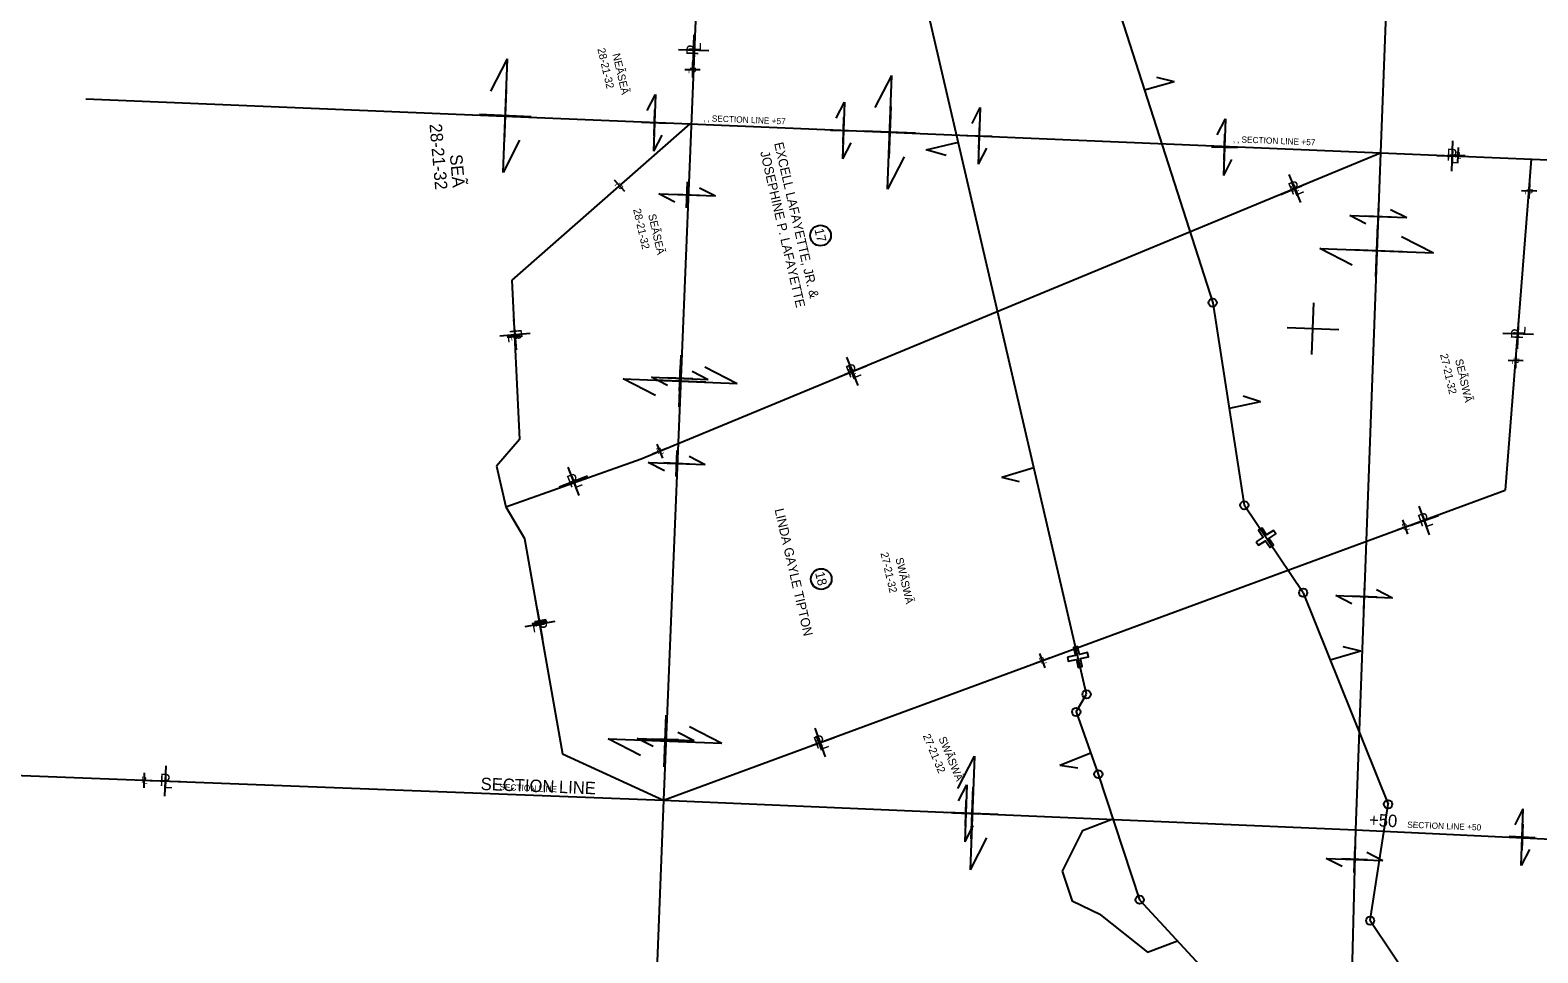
# Model space of a CAD drawing. Extents: x 2814293 to 2835768, y 121185 to 156337.
# Drawn here: x 2819203 to 2822119, y 125490 to 127276 of the extents above; entities that cross this region are included whole.
import ezdxf

# ---------------------------------------------------------------- set-up
doc = ezdxf.new("R2010")
doc.units = 0
for name, color, linetype in [('Default', 7, 'Continuous'), ('Photo-Retaining wall', 7, 'Continuous'), ('Roadway-Alignment notes', 7, 'Continuous'), ('Roadway-Ditches', 7, 'Continuous'), ('Roadway-Edge of pavement', 7, 'Continuous'), ('Roadway-Edge of shoulder', 7, 'Continuous'), ('Roadway-Entrances', 7, 'Continuous'), ('Roadway-New rw', 7, 'Continuous'), ('Roadway-Safety', 7, 'Continuous'), ('Roadway-Temporary easement', 7, 'Continuous'), ('Roadway-Walls', 7, 'Continuous'), ('Scratch-2', 7, 'Continuous'), ('Scratch-5', 7, 'Continuous'), ('Text-New rw label', 7, 'Continuous'), ('Traffic_Control-Traffic barriers', 7, 'Continuous')]:
    doc.layers.add(name, color=color, linetype=linetype)

msp = doc.modelspace()

# ---------------------------------------------------------------- linework, layer by layer
at = {"layer": 'Default'}
for p, q in [((2821682.3, 126648.2), (2821686.1, 126748.2)), ((2821734.2, 126696.2), (2821634.2, 126700.1))]:
    msp.add_line(p, q, dxfattribs=at)
at = {"layer": 'Roadway-Ditches'}
for centre in [(2820731.9, 126878.4), (2820733.3, 126213.7)]:
    msp.add_circle(centre, 20, dxfattribs=at)
at = {"layer": 'Roadway-Edge of pavement'}
for p, q in [((2820396.7, 127120.4), (2820412.6, 127151.6)), ((2820412.6, 127151.6), (2820408.8, 127041.7)), ((2820409.8, 127071.6), (2820411.6, 127121.6)), ((2820762.3, 127105.3), (2820778.2, 127136.5)), ((2820778.2, 127136.5), (2820774.3, 127026.6)), ((2821025, 127095), (2821040.9, 127126.2)), ((2821040.9, 127126.2), (2821037, 127016.3)), ((2820385.7, 127097.5), (2820435.7, 127095.7)), ((2820410.7, 127096.6), (2820410.7, 127096.6)), ((2820775.3, 127056.6), (2820777.1, 127106.5)), ((2821038, 127046.3), (2821039.8, 127096.2)), ((2821499.1, 127073.2), (2821515, 127104.3)), ((2821515, 127104.3), (2821511.1, 126994.4)), ((2820424.7, 127072.8), (2820408.8, 127041.7)), ((2820751.2, 127082.4), (2820801.2, 127080.7)), ((2820790.2, 127057.8), (2820774.3, 127026.6)), ((2820776.2, 127081.6), (2820776.2, 127081.6)), ((2821013.9, 127072.1), (2821063.9, 127070.4)), ((2821038.9, 127071.2), (2821038.9, 127071.2)), ((2821512.2, 127024.4), (2821513.9, 127074.4)), ((2821052.9, 127047.4), (2821037, 127016.3)), ((2821488.1, 127050.3), (2821538, 127048.5)), ((2821527, 127025.6), (2821511.1, 126994.4)), ((2821513.1, 127049.4), (2821513.1, 127049.4)), ((2820472.8, 126932.1), (2820474.7, 126982.1)), ((2820497.6, 126971), (2820528.7, 126954.9)), ((2820418.8, 126959.2), (2820528.7, 126954.9)), ((2820449.9, 126943.2), (2820418.8, 126959.2)), ((2820498.7, 126956.1), (2820448.8, 126958)), ((2820473.7, 126957.1), (2820473.7, 126957.1)), ((2821809.5, 126890.1), (2821811.5, 126940.1)), ((2821755.6, 126917.2), (2821865.5, 126913)), ((2821786.7, 126901.2), (2821755.6, 126917.2)), ((2821835.5, 126914.1), (2821785.5, 126916.1)), ((2821810.5, 126915.1), (2821810.5, 126915.1)), ((2821834.4, 126929), (2821865.5, 126913)), ((2820458.9, 126577.2), (2820460.8, 126627.2)), ((2820483.7, 126616), (2820514.8, 126600)), ((2820404.9, 126604.3), (2820514.8, 126600)), ((2820436, 126588.3), (2820404.9, 126604.3)), ((2820484.9, 126601.2), (2820434.9, 126603.1)), ((2820459.9, 126602.2), (2820459.9, 126602.2)), ((2820452.7, 126412.3), (2820454.7, 126462.3)), ((2820477.5, 126451.2), (2820508.6, 126435.2)), ((2820398.7, 126439.4), (2820508.6, 126435.2)), ((2820429.8, 126423.4), (2820398.7, 126439.4)), ((2820478.7, 126436.3), (2820428.7, 126438.3)), ((2820453.7, 126437.3), (2820453.7, 126437.3)), ((2821728.5, 126181.9), (2821838.4, 126177.6)), ((2821759.6, 126165.9), (2821728.5, 126181.9)), ((2821808.4, 126178.8), (2821758.5, 126180.7)), ((2821782.5, 126154.8), (2821784.4, 126204.7)), ((2821783.4, 126179.7), (2821783.4, 126179.7)), ((2821807.3, 126193.6), (2821838.4, 126177.6)), ((2820431.2, 125878.3), (2820433.1, 125928.3)), ((2820456, 125917.2), (2820487.1, 125901.1)), ((2820377.2, 125905.4), (2820487.1, 125901.1)), ((2820408.3, 125889.4), (2820377.2, 125905.4)), ((2820457.2, 125902.3), (2820407.2, 125904.2)), ((2820432.2, 125903.3), (2820432.2, 125903.3)), ((2820998.9, 125784.3), (2821014.9, 125815.4)), ((2821014.9, 125815.4), (2821010.7, 125705.5)), ((2821011.9, 125735.5), (2821013.8, 125785.4)), ((2820987.8, 125761.4), (2821037.8, 125759.5)), ((2821012.8, 125760.4), (2821012.8, 125760.4)), ((2822075.1, 125738.1), (2822091.1, 125769.3)), ((2822086.9, 125659.3), (2822091.1, 125769.3)), ((2821026.7, 125736.6), (2821010.7, 125705.5)), ((2822114, 125713.3), (2822064, 125715.3)), ((2822090, 125739.3), (2822088, 125689.3)), ((2822089, 125714.3), (2822089, 125714.3)), ((2821763.8, 125646.1), (2821765.7, 125696.1)), ((2821788.6, 125685), (2821819.7, 125669)), ((2822102.9, 125690.5), (2822086.9, 125659.3)), ((2821709.8, 125673.2), (2821819.7, 125669)), ((2821740.9, 125657.2), (2821709.8, 125673.2)), ((2821789.7, 125670.1), (2821739.8, 125672.1)), ((2821764.8, 125671.1), (2821764.8, 125671.1))]:
    msp.add_line(p, q, dxfattribs=at)
at = {"layer": 'Roadway-Edge of shoulder'}
for p, q in [((2820485.3, 127208.1), (2820487.4, 127267)), ((2820456.9, 127238.6), (2820515.8, 127236.5)), ((2821954.2, 127061.8), (2821951.9, 127003)), ((2821923.6, 127033.5), (2821982.5, 127031.3)), ((2821637.6, 126996.6), (2821660.3, 126942.2)), ((2821621.8, 126958.1), (2821676.1, 126980.8)), ((2820138.1, 126715.9), (2820143.2, 126657.2)), ((2822080.1, 126658.9), (2822082.2, 126717.8)), ((2820170, 126689.1), (2820111.3, 126684)), ((2822051.7, 126689.4), (2822110.6, 126687.3)), ((2820765.7, 126604.5), (2820820.5, 126626.2)), ((2820782.3, 126642.8), (2820804, 126588)), ((2820226.3, 126392), (2820281, 126413.7)), ((2820242.8, 126430.2), (2820264.5, 126375.5)), ((2821889.3, 126354.9), (2821909.1, 126299.4)), ((2821871.4, 126317.2), (2821926.9, 126337)), ((2820183.5, 126155.4), (2820194.2, 126097.5)), ((2820217.8, 126131.8), (2820159.9, 126121.1)), ((2820720.8, 125924.9), (2820740.5, 125869.4)), ((2820702.9, 125887.3), (2820758.4, 125907.1)), ((2819465.3, 125852.3), (2819463.1, 125793.5)), ((2819434.8, 125824), (2819493.6, 125821.8))]:
    msp.add_line(p, q, dxfattribs=at)
at = {"layer": 'Roadway-Entrances'}
for p, q in [((2820536.2, 128412.4), (2820428.2, 125785.8)), ((2821840.7, 127719.4), (2821815.2, 127038.4)), ((2821358.3, 127160.2), (2821415.9, 127176.6)), ((2821381.8, 127184.8), (2821415.9, 127176.6)), ((2819310.7, 127143.2), (2820479.2, 127094.3)), ((2820479.2, 127094.3), (2821815.2, 127038.4)), ((2820935.9, 127044.5), (2820998.4, 127058.9)), ((2820974.7, 127033.1), (2820935.9, 127044.5)), ((2821815.2, 127038.4), (2821766.3, 125728.5)), ((2821815.2, 127038.4), (2823145.5, 126981.8)), ((2821582.5, 126556.4), (2821549.3, 126567.5)), ((2821582.5, 126556.4), (2821522.3, 126543.7)), ((2821144.7, 126429), (2821082.7, 126410.2)), ((2821116.8, 126402.1), (2821082.7, 126410.2)), ((2821776.6, 126074.4), (2821717.8, 126056.6)), ((2821776.6, 126074.4), (2821742.6, 126082.6)), ((2815178.3, 125988.3), (2820428.2, 125785.8)), ((2821254.6, 125877.1), (2821194.6, 125852.9)), ((2821229.2, 125847.8), (2821194.6, 125852.9)), ((2820428.2, 125785.8), (2820323.2, 123130.1)), ((2820428.2, 125785.8), (2821766.3, 125728.5)), ((2821766.3, 125728.5), (2821700.5, 123062.8)), ((2821766.3, 125728.5), (2823097.9, 125665))]:
    msp.add_line(p, q, dxfattribs=at)
at = {"layer": 'Roadway-New rw'}
for p, q in [((2821665.3, 126187.2), (2821551.4, 126356.5)), ((2821226.4, 125956.7), (2821246.4, 125990.7)), ((2821226.4, 125956.7), (2821269.1, 125836.2)), ((2821269.1, 125836.2), (2821349, 125593.1)), ((2821794.9, 125552.8), (2821829.6, 125778)), ((2821349, 125593.1), (2821596.6, 125325.2)), ((2821794.9, 125552.8), (2822050.4, 125173.6))]:
    msp.add_line(p, q, dxfattribs=at)
for points in [[(2821246.4, 125990.7), (2820901.3, 127477.3)], [(2821295.1, 127357.3), (2821490.4, 126748.5)], [(2821490.4, 126748.5), (2821551.4, 126356.5)], [(2821665.3, 126187.2), (2821829.6, 125778)]]:
    msp.add_lwpolyline(points, dxfattribs=at)
for points in [[(2821574.7, 126285.8), (2821579.1, 126279.1), (2821592.5, 126287.9), (2821601.3, 126274.6), (2821608, 126279), (2821599.1, 126292.4), (2821612.5, 126301.2), (2821608.1, 126307.9), (2821594.7, 126299), (2821585.9, 126312.4), (2821579.2, 126308), (2821588.1, 126294.6), (2821574.7, 126285.8)], [(2821209.3, 126062.4), (2821211.1, 126054.6), (2821226.7, 126058.2), (2821230.2, 126042.6), (2821238, 126044.3), (2821234.5, 126059.9), (2821250.1, 126063.5), (2821248.3, 126071.3), (2821232.7, 126067.7), (2821229.1, 126083.3), (2821221.3, 126081.5), (2821224.9, 126065.9), (2821209.3, 126062.4)]]:
    msp.add_lwpolyline(points, close=True, dxfattribs=at)
at = {"layer": 'Roadway-Temporary easement'}
for p, q in [((2821238.6, 125727.4), (2821297.4, 125750)), ((2821238.6, 125727.4), (2821199.2, 125648.6)), ((2821199.2, 125648.6), (2821218.2, 125590.6)), ((2821273.5, 125564), (2821218.2, 125590.6)), ((2821273.5, 125564), (2821364, 125491.7)), ((2821364, 125491.7), (2821422.1, 125514))]:
    msp.add_line(p, q, dxfattribs=at)
at = {"layer": 'Roadway-Walls'}
for p, q in [((2820484.1, 127213.6), (2820484, 127184.2)), ((2820498.8, 127198.8), (2820469.3, 127199)), ((2821949.4, 127034.4), (2821978.9, 127033.2)), ((2821964.8, 127048.5), (2821963.5, 127019.1)), ((2820354, 126984.7), (2820332.3, 126964.7)), ((2820353.1, 126963.9), (2820333.2, 126985.5)), ((2821634.7, 126963.4), (2821661.9, 126974.7)), ((2821642.7, 126982.6), (2821654, 126955.4)), ((2822102.9, 126979.2), (2822101.8, 126949.8)), ((2822117.1, 126964), (2822087.6, 126965)), ((2820155.3, 126683.8), (2820125.9, 126681.3)), ((2820139.3, 126697.2), (2820141.9, 126667.9)), ((2822076.7, 126651), (2822075.7, 126621.5)), ((2820777.9, 126609.4), (2820805.2, 126620.3)), ((2820786.1, 126628.5), (2820797, 126601.1)), ((2822090.9, 126635.7), (2822061.5, 126636.8)), ((2820415, 126475), (2820425.9, 126447.6)), ((2820406.7, 126455.9), (2820434.1, 126466.8)), ((2821857.5, 126328.3), (2821867.4, 126300.6)), ((2821848.6, 126309.5), (2821876.3, 126319.4)), ((2820202.6, 126132.2), (2820173.6, 126126.9)), ((2820185.4, 126144.1), (2820190.7, 126115.1)), ((2821155.5, 126069.6), (2821165.9, 126042.1)), ((2821146.9, 126050.7), (2821174.5, 126061.1)), ((2820714.6, 125891.4), (2820742.4, 125901.3)), ((2820723.6, 125910.2), (2820733.5, 125882.4)), ((2819423.9, 125839), (2819422.8, 125809.6)), ((2819408.6, 125824.9), (2819438, 125823.8))]:
    msp.add_line(p, q, dxfattribs=at)
at = {"layer": 'Scratch-2'}
for p, q in [((2820094.3, 127158), (2820126.3, 127220.3)), ((2820117.8, 127000.4), (2820126.3, 127220.3)), ((2820837.8, 127125.9), (2820869.9, 127188.1)), ((2820861.3, 126968.3), (2820869.9, 127188.1)), ((2820124, 127160.3), (2820120.1, 127060.4)), ((2820172, 127108.4), (2820072.1, 127112.3)), ((2820867.5, 127128.2), (2820863.7, 127028.2)), ((2820122.1, 127110.3), (2820122.1, 127110.3)), ((2820149.8, 127062.7), (2820117.8, 127000.4)), ((2820915.6, 127076.3), (2820815.6, 127080.1)), ((2820865.6, 127078.2), (2820865.6, 127078.2)), ((2820893.3, 127030.5), (2820861.3, 126968.3)), ((2821805.7, 126799.1), (2821809.6, 126899)), ((2821697.7, 126853.3), (2821917.5, 126844.8)), ((2821760, 126821.3), (2821697.7, 126853.3)), ((2821857.6, 126847.1), (2821757.7, 126851)), ((2821855.3, 126876.8), (2821917.5, 126844.8)), ((2821807.6, 126849), (2821807.6, 126849)), ((2820458.4, 126546.7), (2820462.3, 126646.6)), ((2820508, 126624.4), (2820570.3, 126592.4)), ((2820350.4, 126600.9), (2820570.3, 126592.4)), ((2820412.7, 126568.9), (2820350.4, 126600.9)), ((2820510.3, 126594.7), (2820410.4, 126598.6)), ((2820460.4, 126596.6), (2820460.4, 126596.6)), ((2820429.1, 125850.4), (2820433, 125950.3)), ((2820478.7, 125928.1), (2820541, 125896.1)), ((2820321.2, 125904.6), (2820541, 125896.1)), ((2820383.4, 125872.6), (2820321.2, 125904.6)), ((2820481, 125898.4), (2820381.1, 125902.3)), ((2820431.1, 125900.4), (2820431.1, 125900.4)), ((2820997.4, 125808.5), (2821029.4, 125870.8)), ((2821029.4, 125870.8), (2821021.1, 125651)), ((2821023.3, 125710.9), (2821027.1, 125810.8)), ((2820975.3, 125762.8), (2821075.2, 125759)), ((2821025.2, 125760.9), (2821025.2, 125760.9)), ((2821053, 125713.2), (2821021.1, 125651))]:
    msp.add_line(p, q, dxfattribs=at)
at = {"layer": 'Text-New rw label'}
for centre in [(2821490.4, 126748.5), (2821551.4, 126356.5), (2821665.3, 126187.2), (2821246.4, 125990.7), (2821226.4, 125956.7), (2821269.1, 125836.2), (2821829.6, 125778), (2821349, 125593.1), (2821794.9, 125552.8)]:
    msp.add_circle(centre, 8, dxfattribs=at)
at = {"layer": 'Traffic_Control-Traffic barriers'}
for p, q in [((2820479.2, 127094.3), (2820134.6, 126792.2)), ((2822106.4, 127026), (2822055.8, 126385.9)), ((2820134.6, 126792.2), (2820149.6, 126483.7)), ((2820149.6, 126483.7), (2820105, 126432.1)), ((2820105, 126432.1), (2820123.3, 126353.4)), ((2820428.2, 125785.8), (2822055.8, 126385.9)), ((2820123.3, 126353.4), (2820159.4, 126292.4)), ((2820159.4, 126292.4), (2820232.5, 125875.8)), ((2820232.5, 125875.8), (2820428.2, 125785.8))]:
    msp.add_line(p, q, dxfattribs=at)
msp.add_lwpolyline([(2820123.3, 126353.4), (2820384.6, 126446.5), (2821815.2, 127038.4)], dxfattribs=at)

# ---------------------------------------------------------------- texts
at = {"layer": 'Photo-Retaining wall'}
for s, rotation, p in [('28-21-32', 283.038, (2820300.2, 127239.5)), ('NEÃSEÃ', 283.038, (2820329.2, 127229.2)), ('28-21-32', 283.038, (2820369.2, 126928.8)), ('SEÃSEÃ', 283.038, (2820398.3, 126918.5)), ('27-21-32', 283.038, (2821930, 126648.1)), ('SEÃSWÃ', 283.038, (2821959.1, 126637.8)), ('27-21-32', 283.038, (2820847.7, 126263.7)), ('SWÃSWÃ', 283.038, (2820876.7, 126253.4)), ('27-21-32', 292.7163, (2820929.3, 125910.5)), ('SWÃSWÃ', 292.7163, (2820959.7, 125905.3))]:
    msp.add_text(s, height=15, rotation=rotation, dxfattribs=at).set_placement(p)
at = {"layer": 'Roadway-Alignment notes'}
for s, p in [('28-21-32', (2819975.4, 127093.8)), ('SEÃ', (2820014.8, 127034.5))]:
    msp.add_text(s, height=24, rotation=275.0693, dxfattribs=at).set_placement(p)
at = {"layer": 'Roadway-Ditches'}
for s, p in [('EXCELL LAFAYETTE, JR. &', (2820641.9, 127056.7)), ('JOSEPHINE P. LAFAYETTE', (2820615, 127039.8)), ('17', (2820719.9, 126890.2)), ('LINDA GAYLE TIPTON', (2820642.8, 126348.1)), ('18', (2820721.3, 126225.5))]:
    msp.add_text(s, height=18, rotation=283.038, dxfattribs=at).set_placement(p)
at = {"layer": 'Roadway-Edge of shoulder'}
for s, rotation, p in [('P', 87.9775, (2820495.6, 127226.6)), ('L', 87.9775, (2820500.2, 127234.4)), ('P', 357.7804, (2821942, 127023.2)), ('L', 357.7804, (2821949.8, 127018.6)), ('P', 22.6261, (2821642.8, 126956.4)), ('L', 22.6261, (2821651.8, 126955.5)), ('L', 274.9572, (2820126.5, 126688)), ('P', 274.9572, (2820130.1, 126696.4)), ('P', 87.9775, (2822090.4, 126677.3)), ('L', 87.9775, (2822095, 126685.2)), ('P', 21.6261, (2820786.7, 126602.5)), ('L', 21.6261, (2820795.7, 126601.5)), ('P', 21.6261, (2820247.3, 126390)), ('L', 21.6261, (2820256.3, 126388.9)), ('P', 19.6261, (2821892.4, 126314.5)), ('L', 19.6261, (2821901.3, 126313.1)), ('L', 280.4559, (2820174.7, 126126.6)), ('P', 280.4559, (2820177.5, 126135.2)), ('P', 19.6261, (2820723.8, 125884.5)), ('L', 19.6261, (2820732.8, 125883.1)), ('P', 357.7804, (2819453.2, 125813.7)), ('L', 357.7804, (2819461, 125809.1))]:
    msp.add_text(s, height=23.6, rotation=rotation, dxfattribs=at).set_placement(p)
at = {"layer": 'Roadway-Safety'}
for s, p in [('‚ ‚ SECTION LINE +57', (2820505.3, 127099.6)), ('‚ ‚ SECTION LINE +57', (2821529.8, 127058.9)), ('SECTION LINE', (2820110.6, 125805.5)), ('SECTION LINE +50', (2821866.4, 125732.6))]:
    msp.add_text(s, height=12, rotation=357.7804, dxfattribs=at).set_placement(p)
at = {"layer": 'Roadway-Walls'}
for s, rotation, p in [('P', 269.6261, (2820479.3, 127204.3)), ('L', 269.6261, (2820477.1, 127200.3)), ('P', 357.6261, (2821958.6, 127029.2)), ('L', 357.6261, (2821962.5, 127026.9)), ('L', 222.6261, (2820339.4, 126980.7)), ('P', 222.6261, (2820343.8, 126981.9)), ('P', 22.6261, (2821645.2, 126962.5)), ('L', 22.6261, (2821649.8, 126962.1)), ('P', 267.9775, (2822097.7, 126970)), ('L', 267.9775, (2822095.4, 126966.1)), ('L', 274.9572, (2820133.6, 126683.3)), ('P', 274.9572, (2820135.4, 126687.4)), ('P', 21.6261, (2820788.4, 126608.4)), ('L', 21.6261, (2820792.9, 126607.9)), ('L', 267.9775, (2822069.3, 126637.8)), ('P', 267.9775, (2822071.6, 126641.8)), ('P', 21.6261, (2820417.2, 126454.9)), ('L', 21.6261, (2820421.7, 126454.4)), ('P', 19.6261, (2821859, 126308.1)), ('L', 19.6261, (2821863.5, 126307.4)), ('L', 280.4559, (2820181, 126129.6)), ('P', 280.4559, (2820182.4, 126133.9)), ('P', 20.6261, (2821157.4, 126049.5)), ('L', 20.6261, (2821161.9, 126048.9)), ('P', 19.6261, (2820725.1, 125890)), ('L', 19.6261, (2820729.6, 125889.3)), ('P', 357.7804, (2819417.8, 125819.7)), ('L', 357.7804, (2819421.7, 125817.4))]:
    msp.add_text(s, height=11.8, rotation=rotation, dxfattribs=at).set_placement(p)
at = {"layer": 'Scratch-5'}
for s, rotation, p in [('SECTION LINE', 357.7804, (2820074.1, 125805.7)), ('+50', 357.2938, (2821792.3, 125736))]:
    msp.add_text(s, height=24, rotation=rotation, dxfattribs=at).set_placement(p)

doc.saveas('drawing.dxf')
